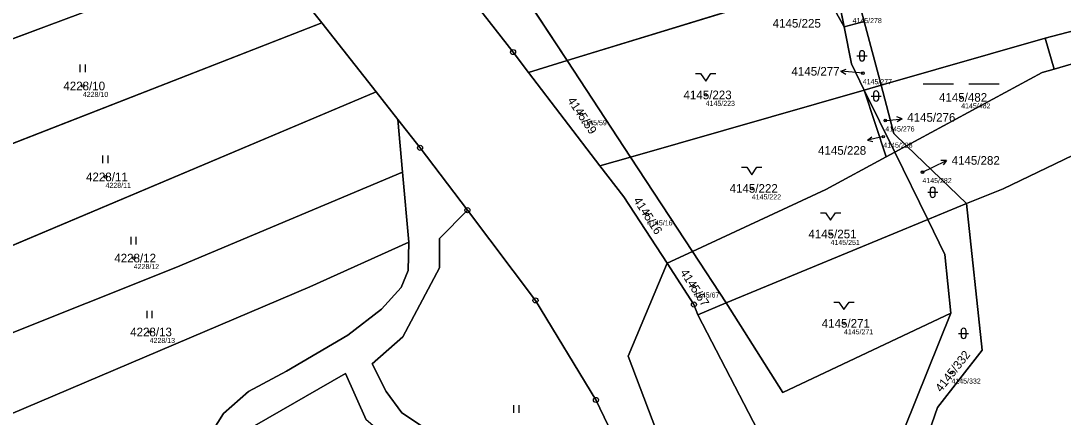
# Model space of a CAD drawing. Extents: x -739214 to -733252, y -1147612 to -1142842.
# Drawn here: x -736633.4 to -736428.1, y -1146634 to -1146556 of the extents above; entities that cross this region are included whole.
import ezdxf

# ---------------------------------------------------------------- set-up
doc = ezdxf.new("R2010")
doc.units = 0
for name, color, linetype in [('Definiční body', 7, 'Continuous'), ('Hranice parcel', 7, 'Continuous'), ('Parcelní čísla', 7, 'Continuous'), ('Polygon parcely', 7, 'Continuous'), ('Pop  PČ popisy', 7, 'Continuous'), ('Značky bodu BP', 7, 'Continuous'), ('Značky kultur', 7, 'Continuous')]:
    doc.layers.add(name, color=color, linetype=linetype)

msp = doc.modelspace()

# ---------------------------------------------------------------- linework, layer by layer
at = {"layer": 'Definiční body'}
for centre in [(-736467.6, -1146566.26), (-736621.18, -1146568.77), (-736498.53, -1146570.53), (-736448.22, -1146571.02), (-736523, -1146574.35), (-736463.16, -1146575.57), (-736463.56, -1146578.75), (-736455.85, -1146585.73), (-736616.71, -1146586.67), (-736489.45, -1146588.94), (-736510.05, -1146594.06), (-736473.94, -1146597.91), (-736611.15, -1146602.65), (-736500.83, -1146608.26), (-736608.02, -1146617.2), (-736471.31, -1146615.5), (-736450.13, -1146625.2)]:
    msp.add_circle(centre, 0.25, dxfattribs=at)
at = {"layer": 'Hranice parcel'}
for p, q in [((-736525.83, -1146563.74), (-736542.94, -1146537.7)), ((-736658.72, -1146568.3), (-736585.12, -1146540.83)), ((-736467.33, -1146556.06), (-736469.8, -1146546.72)), ((-736476.06, -1146548.51), (-736525.83, -1146563.74)), ((-736471.29, -1146557.11), (-736476.06, -1146548.51)), ((-736471.29, -1146557.11), (-736473.17, -1146547.68)), ((-736574.11, -1146556.35), (-736578.57, -1146550.68)), ((-736658.16, -1146589.11), (-736574.11, -1146556.35)), ((-736563.42, -1146569.94), (-736574.11, -1146556.35)), ((-736467.33, -1146556.06), (-736471.29, -1146557.11)), ((-736464, -1146568.64), (-736467.33, -1146556.06)), ((-736431.69, -1146559.38), (-736464, -1146568.64)), ((-736431.69, -1146559.38), (-736429.94, -1146565.44)), ((-736525.83, -1146563.74), (-736533.42, -1146566.09)), ((-736513.33, -1146582.77), (-736525.83, -1146563.74)), ((-736533.42, -1146566.09), (-736519.36, -1146584.5)), ((-736467.3, -1146569.58), (-736513.33, -1146582.77)), ((-736464, -1146568.64), (-736467.3, -1146569.58)), ((-736463, -1146582.72), (-736467.3, -1146569.58)), ((-736461.31, -1146581.81), (-736467.3, -1146569.58)), ((-736659.28, -1146610.36), (-736563.42, -1146569.94)), ((-736559.13, -1146575.4), (-736563.42, -1146569.94)), ((-736554.77, -1146580.95), (-736559.13, -1146575.4)), ((-736558.25, -1146585.73), (-736559.13, -1146575.4)), ((-736545.45, -1146593.22), (-736554.77, -1146580.95)), ((-736463, -1146582.72), (-736461.31, -1146581.81)), ((-736461.31, -1146581.81), (-736458.98, -1146580.55)), ((-736454.82, -1146595.05), (-736461.31, -1146581.81)), ((-736447.19, -1146591.89), (-736458.98, -1146580.55)), ((-736513.33, -1146582.77), (-736519.36, -1146584.5)), ((-736501.13, -1146601.35), (-736513.33, -1146582.77)), ((-736557.02, -1146599.49), (-736558.25, -1146585.73)), ((-736454.82, -1146595.05), (-736447.19, -1146591.89)), ((-736494.48, -1146611.47), (-736454.82, -1146595.05)), ((-736451.43, -1146601.95), (-736454.82, -1146595.05)), ((-736506.14, -1146603.68), (-736501.13, -1146601.35)), ((-736494.48, -1146611.47), (-736501.13, -1146601.35)), ((-736450.23, -1146613.49), (-736451.43, -1146601.95)), ((-736494.48, -1146611.47), (-736500.11, -1146613.8)), ((-736500.11, -1146613.8), (-736488.24, -1146636.62))]:
    msp.add_line(p, q, dxfattribs=at)
for points in [[(-736429.94, -1146565.44), (-736339.52, -1146538.9), (-736337.25, -1146534.6), (-736431.69, -1146559.38)], [(-736447.19, -1146591.89), (-736439.96, -1146588.99), (-736395.44, -1146567.64), (-736364.43, -1146560.32), (-736344.54, -1146555.23), (-736308.59, -1146573.63), (-736302.45, -1146556.76), (-736312.57, -1146537.18)], [(-736553, -1146540.95), (-736536.46, -1146562.1), (-736533.42, -1146566.09)], [(-736467.3, -1146569.58), (-736469.84, -1146564.41), (-736471.29, -1146557.11)], [(-736458.98, -1146580.55), (-736432.29, -1146566.13), (-736429.94, -1146565.44)], [(-736458.98, -1146580.55), (-736461.49, -1146578.14), (-736464, -1146568.64)], [(-736501.13, -1146601.35), (-736474.85, -1146589.12), (-736463, -1146582.72)], [(-736656.03, -1146625.69), (-736602.87, -1146604.51), (-736558.25, -1146585.73)], [(-736519.36, -1146584.5), (-736514.68, -1146590.62), (-736506.14, -1146603.68)], [(-736446.12, -1146664.77), (-736455.11, -1146638.49), (-736452.89, -1146632.08), (-736444.11, -1146620.77), (-736447.19, -1146591.89)], [(-736545.45, -1146593.22), (-736550.98, -1146598.79), (-736550.98, -1146604.55), (-736558.14, -1146618.12), (-736564.23, -1146623.46), (-736561.45, -1146628.91), (-736558.35, -1146633.08), (-736546.18, -1146641.2), (-736541.16, -1146645.36), (-736539.55, -1146648.78), (-736538.61, -1146656.96)], [(-736509.65, -1146652.42), (-736520.15, -1146630.58), (-736532.04, -1146610.98), (-736545.45, -1146593.22)], [(-736650.47, -1146639.75), (-736576.48, -1146608.33), (-736557.02, -1146599.49)], [(-736615.59, -1146662.7), (-736613.37, -1146659.3), (-736608.45, -1146653.82), (-736602.19, -1146647.11), (-736593.46, -1146633.23), (-736588.56, -1146628.91), (-736581.07, -1146624.89), (-736568.99, -1146617.84), (-736562.39, -1146612.69), (-736558.47, -1146608.44), (-736557.13, -1146605.08), (-736557.02, -1146599.49)], [(-736473.74, -1146679.1), (-736501.96, -1146653.1), (-736513.77, -1146621.93), (-736506.14, -1146603.68)], [(-736506.14, -1146603.68), (-736500.84, -1146611.78), (-736500.11, -1146613.8)], [(-736450.23, -1146613.49), (-736483.35, -1146629.09), (-736494.48, -1146611.47)], [(-736449.18, -1146674.88), (-736461.75, -1146642.02), (-736450.23, -1146613.49)], [(-736562.32, -1146637.09), (-736565.4, -1146634.47), (-736569.46, -1146625.39), (-736587.4, -1146635.64), (-736590.61, -1146638.74), (-736596.04, -1146648.74), (-736606.3, -1146660.49), (-736609.82, -1146666.47), (-736610.25, -1146670.85), (-736609.18, -1146673.63), (-736604.38, -1146677.69), (-736598.61, -1146681.53), (-736591.56, -1146688.26), (-736588.67, -1146694.43), (-736582.05, -1146714.94), (-736578.89, -1146719.08)]]:
    msp.add_lwpolyline(points, dxfattribs=at)
at = {"layer": 'Polygon parcely'}
for points in [[(-736476.06, -1146548.51), (-736480.2, -1146538.83), (-736489.9, -1146520.56), (-736542.94, -1146537.7), (-736525.83, -1146563.74)], [(-736593.58, -1146525.58), (-736661.58, -1146551.89), (-736661.29, -1146553.19), (-736658.72, -1146568.3), (-736585.12, -1146540.83)], [(-736431.69, -1146559.38), (-736429.94, -1146565.44), (-736339.52, -1146538.9), (-736337.25, -1146534.6)], [(-736536.46, -1146562.1), (-736533.42, -1146566.09), (-736525.83, -1146563.74), (-736542.94, -1146537.7), (-736553, -1146540.95)], [(-736585.12, -1146540.83), (-736658.72, -1146568.3), (-736657.71, -1146577.58), (-736658.16, -1146589.11), (-736574.11, -1146556.35), (-736578.57, -1146550.68), (-736583.5, -1146553.48), (-736588.45, -1146544.55), (-736584.27, -1146542.36)], [(-736467.33, -1146556.06), (-736469.8, -1146546.72), (-736473.17, -1146547.68), (-736471.29, -1146557.11)], [(-736467.3, -1146569.58), (-736469.84, -1146564.41), (-736471.29, -1146557.11), (-736476.06, -1146548.51), (-736525.83, -1146563.74), (-736513.33, -1146582.77)], [(-736471.29, -1146557.11), (-736473.17, -1146547.68), (-736476.06, -1146548.51)], [(-736659.28, -1146610.36), (-736563.42, -1146569.94), (-736574.11, -1146556.35), (-736658.16, -1146589.11)], [(-736464, -1146568.64), (-736467.33, -1146556.06), (-736471.29, -1146557.11), (-736469.84, -1146564.41), (-736467.3, -1146569.58)], [(-736458.98, -1146580.55), (-736432.29, -1146566.13), (-736429.94, -1146565.44), (-736431.69, -1146559.38), (-736464, -1146568.64), (-736461.49, -1146578.14)], [(-736525.83, -1146563.74), (-736533.42, -1146566.09), (-736519.36, -1146584.5), (-736513.33, -1146582.77)], [(-736501.13, -1146601.35), (-736474.85, -1146589.12), (-736463, -1146582.72), (-736467.3, -1146569.58), (-736513.33, -1146582.77)], [(-736467.3, -1146569.58), (-736461.31, -1146581.81), (-736458.98, -1146580.55), (-736461.49, -1146578.14), (-736464, -1146568.64)], [(-736463, -1146582.72), (-736461.31, -1146581.81), (-736467.3, -1146569.58)], [(-736656.03, -1146625.69), (-736602.87, -1146604.51), (-736558.25, -1146585.73), (-736559.13, -1146575.4), (-736563.42, -1146569.94), (-736659.28, -1146610.36), (-736659.39, -1146612.71)], [(-736494.48, -1146611.47), (-736454.82, -1146595.05), (-736461.31, -1146581.81), (-736463, -1146582.72), (-736474.85, -1146589.12), (-736501.13, -1146601.35)], [(-736454.82, -1146595.05), (-736447.19, -1146591.89), (-736458.98, -1146580.55), (-736461.31, -1146581.81)], [(-736506.14, -1146603.68), (-736501.13, -1146601.35), (-736513.33, -1146582.77), (-736519.36, -1146584.5), (-736514.68, -1146590.62)], [(-736650.47, -1146639.75), (-736576.48, -1146608.33), (-736557.02, -1146599.49), (-736558.25, -1146585.73), (-736602.87, -1146604.51), (-736656.03, -1146625.69)], [(-736446.12, -1146664.77), (-736455.11, -1146638.49), (-736452.89, -1146632.08), (-736444.11, -1146620.77), (-736447.19, -1146591.89), (-736454.82, -1146595.05), (-736451.43, -1146601.95), (-736450.23, -1146613.49), (-736461.75, -1146642.02), (-736449.18, -1146674.88)], [(-736520.15, -1146630.58), (-736532.04, -1146610.98), (-736545.45, -1146593.22), (-736550.98, -1146598.79), (-736550.98, -1146604.55), (-736558.14, -1146618.12), (-736564.23, -1146623.46), (-736561.45, -1146628.91), (-736558.35, -1146633.08), (-736546.18, -1146641.2), (-736541.16, -1146645.36), (-736539.55, -1146648.78), (-736538.61, -1146656.96), (-736509.65, -1146652.42)], [(-736451.43, -1146601.95), (-736454.82, -1146595.05), (-736494.48, -1146611.47), (-736483.35, -1146629.09), (-736450.23, -1146613.49)], [(-736557.13, -1146605.08), (-736557.02, -1146599.49), (-736576.48, -1146608.33), (-736650.47, -1146639.75), (-736650, -1146641.67), (-736644, -1146658.32), (-736615.59, -1146662.7), (-736613.37, -1146659.3), (-736608.45, -1146653.82), (-736602.19, -1146647.11), (-736593.46, -1146633.23), (-736588.56, -1146628.91), (-736581.07, -1146624.89), (-736568.99, -1146617.84), (-736562.39, -1146612.69), (-736558.47, -1146608.44)], [(-736500.11, -1146613.8), (-736494.48, -1146611.47), (-736501.13, -1146601.35), (-736506.14, -1146603.68), (-736500.84, -1146611.78)], [(-736488.24, -1146636.62), (-736500.11, -1146613.8), (-736500.84, -1146611.78), (-736506.14, -1146603.68), (-736513.77, -1146621.93), (-736501.96, -1146653.1), (-736473.74, -1146679.1), (-736479.13, -1146660.55)], [(-736467.13, -1146769.67), (-736467.49, -1146772.99), (-736383.21, -1146801.37), (-736381.77, -1146800.87), (-736378.06, -1146705.71), (-736425.61, -1146677.71), (-736449.18, -1146674.88), (-736461.75, -1146642.02), (-736450.23, -1146613.49), (-736483.35, -1146629.09), (-736494.48, -1146611.47), (-736500.11, -1146613.8), (-736488.24, -1146636.62), (-736479.13, -1146660.55), (-736473.74, -1146679.1), (-736470.53, -1146684.2), (-736467.08, -1146690.31), (-736469.67, -1146697.93), (-736467.34, -1146711.33), (-736465.52, -1146735.67)], [(-736587.4, -1146635.64), (-736590.61, -1146638.74), (-736596.04, -1146648.74), (-736606.3, -1146660.49), (-736609.82, -1146666.47), (-736610.25, -1146670.85), (-736609.18, -1146673.63), (-736604.38, -1146677.69), (-736598.61, -1146681.53), (-736591.56, -1146688.26), (-736588.67, -1146694.43), (-736582.05, -1146714.94), (-736578.89, -1146719.08), (-736579.32, -1146693.66), (-736562.32, -1146637.09), (-736565.4, -1146634.47), (-736569.46, -1146625.39)]]:
    msp.add_lwpolyline(points, close=True, dxfattribs=at)
for points in [[(-736469.8, -1146546.72), (-736467.33, -1146556.06), (-736464, -1146568.64), (-736431.69, -1146559.38), (-736337.25, -1146534.6)], [(-736339.52, -1146538.9), (-736429.94, -1146565.44), (-736432.29, -1146566.13), (-736458.98, -1146580.55), (-736447.19, -1146591.89), (-736439.96, -1146588.99), (-736395.44, -1146567.64), (-736364.43, -1146560.32), (-736344.54, -1146555.23), (-736308.59, -1146573.63), (-736302.45, -1146556.76), (-736312.57, -1146537.18)], [(-736312.57, -1146537.18), (-736302.45, -1146556.76), (-736308.59, -1146573.63), (-736344.54, -1146555.23), (-736364.43, -1146560.32), (-736395.44, -1146567.64), (-736439.96, -1146588.99), (-736447.19, -1146591.89), (-736444.11, -1146620.77), (-736452.89, -1146632.08), (-736455.11, -1146638.49), (-736446.12, -1146664.77), (-736250, -1146692.16)], [(-736501.96, -1146653.1), (-736513.77, -1146621.93), (-736506.14, -1146603.68), (-736514.68, -1146590.62), (-736519.36, -1146584.5), (-736533.42, -1146566.09), (-736536.46, -1146562.1), (-736553, -1146540.95)], [(-736578.57, -1146550.68), (-736574.11, -1146556.35), (-736563.42, -1146569.94), (-736559.13, -1146575.4), (-736554.77, -1146580.95), (-736545.45, -1146593.22), (-736532.04, -1146610.98), (-736520.15, -1146630.58), (-736509.65, -1146652.42)], [(-736546.18, -1146641.2), (-736558.35, -1146633.08), (-736561.45, -1146628.91), (-736564.23, -1146623.46), (-736558.14, -1146618.12), (-736550.98, -1146604.55), (-736550.98, -1146598.79), (-736545.45, -1146593.22), (-736554.77, -1146580.95), (-736559.13, -1146575.4), (-736558.25, -1146585.73), (-736557.02, -1146599.49), (-736557.13, -1146605.08), (-736558.47, -1146608.44), (-736562.39, -1146612.69), (-736568.99, -1146617.84), (-736581.07, -1146624.89), (-736588.56, -1146628.91), (-736593.46, -1146633.23), (-736602.19, -1146647.11)], [(-736587.4, -1146635.64), (-736569.46, -1146625.39), (-736565.4, -1146634.47)]]:
    msp.add_lwpolyline(points, dxfattribs=at)
at = {"layer": 'Pop  PČ popisy'}
for p, q in [((-736471.9, -1146565.88), (-736470.86, -1146565.47)), ((-736468.91, -1146566.14), (-736471.9, -1146565.88)), ((-736471.9, -1146565.88), (-736470.95, -1146566.47)), ((-736467.6, -1146566.26), (-736468.91, -1146566.14)), ((-736463.16, -1146575.57), (-736462.84, -1146575.54)), ((-736462.84, -1146575.54), (-736459.85, -1146575.23)), ((-736459.85, -1146575.23), (-736460.9, -1146574.83)), ((-736459.85, -1146575.23), (-736460.8, -1146575.83)), ((-736466.67, -1146579.47), (-736465.81, -1146578.75)), ((-736463.75, -1146578.79), (-736466.67, -1146579.47)), ((-736466.67, -1146579.47), (-736465.59, -1146579.73)), ((-736463.56, -1146578.75), (-736463.75, -1146578.79)), ((-736453.8, -1146584.74), (-736451.1, -1146583.42)), ((-736451.1, -1146583.42), (-736452.22, -1146583.41)), ((-736451.1, -1146583.42), (-736451.78, -1146584.31)), ((-736455.85, -1146585.73), (-736453.8, -1146584.74))]:
    msp.add_line(p, q, dxfattribs=at)
at = {"layer": 'Značky bodu BP'}
for centre, radius in [((-736536.46, -1146562.1), 0.5), ((-736536.46, -1146562.1), 0.0303), ((-736554.77, -1146580.95), 0.5), ((-736554.77, -1146580.95), 0.0303), ((-736545.45, -1146593.22), 0.5), ((-736545.45, -1146593.22), 0.0303), ((-736532.04, -1146610.98), 0.5), ((-736532.04, -1146610.98), 0.0303), ((-736500.84, -1146611.78), 0.5), ((-736500.84, -1146611.78), 0.0303), ((-736520.15, -1146630.58), 0.5), ((-736520.15, -1146630.58), 0.0303)]:
    msp.add_circle(centre, radius, dxfattribs=at)
at = {"layer": 'Značky kultur'}
for p, q in [((-736468.74, -1146562.83), (-736466.74, -1146562.83)), ((-736468.24, -1146562.33), (-736468.24, -1146563.33)), ((-736467.24, -1146563.33), (-736467.24, -1146562.33)), ((-736621.69, -1146566.07), (-736621.69, -1146564.57)), ((-736620.69, -1146566.07), (-736620.69, -1146564.57)), ((-736500.53, -1146566.33), (-736499.53, -1146566.33)), ((-736499.53, -1146566.33), (-736498.53, -1146567.83)), ((-736498.53, -1146567.83), (-736497.53, -1146566.33)), ((-736497.53, -1146566.33), (-736496.53, -1146566.33)), ((-736455.71, -1146568.32), (-736449.71, -1146568.32)), ((-736446.71, -1146568.32), (-736440.71, -1146568.32)), ((-736465.97, -1146570.75), (-736463.97, -1146570.75)), ((-736465.47, -1146570.25), (-736465.47, -1146571.25)), ((-736464.47, -1146571.25), (-736464.47, -1146570.25)), ((-736617.22, -1146583.97), (-736617.22, -1146582.47)), ((-736616.22, -1146583.97), (-736616.22, -1146582.47)), ((-736491.45, -1146584.74), (-736490.45, -1146584.74)), ((-736490.45, -1146584.74), (-736489.45, -1146586.24)), ((-736489.45, -1146586.24), (-736488.45, -1146584.74)), ((-736488.45, -1146584.74), (-736487.45, -1146584.74)), ((-736454.82, -1146589.7), (-736452.82, -1146589.7)), ((-736454.32, -1146589.2), (-736454.32, -1146590.2)), ((-736453.32, -1146590.2), (-736453.32, -1146589.2)), ((-736475.94, -1146593.71), (-736474.94, -1146593.71)), ((-736474.94, -1146593.71), (-736473.94, -1146595.21)), ((-736473.94, -1146595.21), (-736472.94, -1146593.71)), ((-736472.94, -1146593.71), (-736471.94, -1146593.71)), ((-736611.66, -1146599.95), (-736611.66, -1146598.45)), ((-736610.66, -1146599.95), (-736610.66, -1146598.45)), ((-736608.53, -1146614.5), (-736608.53, -1146613)), ((-736607.53, -1146614.5), (-736607.53, -1146613)), ((-736473.31, -1146611.3), (-736472.31, -1146611.3)), ((-736472.31, -1146611.3), (-736471.31, -1146612.8)), ((-736471.31, -1146612.8), (-736470.31, -1146611.3)), ((-736470.31, -1146611.3), (-736469.31, -1146611.3)), ((-736448.25, -1146616.97), (-736448.25, -1146617.97)), ((-736447.25, -1146617.97), (-736447.25, -1146616.97)), ((-736448.75, -1146617.47), (-736446.75, -1146617.47)), ((-736536.28, -1146633.08), (-736536.28, -1146631.58)), ((-736535.28, -1146633.08), (-736535.28, -1146631.58))]:
    msp.add_line(p, q, dxfattribs=at)
for centre, start, end in [((-736467.74, -1146562.33), 0, 180), ((-736467.74, -1146563.33), 180, 359.9879), ((-736464.97, -1146570.25), 0, 180), ((-736464.97, -1146571.25), 180, 359.9879), ((-736453.82, -1146589.2), 0, 180), ((-736453.82, -1146590.2), 180, 359.9879), ((-736447.75, -1146616.97), 0, 180), ((-736447.75, -1146617.97), 180, 359.9879)]:
    msp.add_arc(centre, 0.5, start, end, dxfattribs=at)

# ---------------------------------------------------------------- texts
at = {"layer": 'Definiční body'}
for s, p in [('4145/278', (-736469.61, -1146556.4)), ('4145/277', (-736467.6, -1146568.42)), ('4228/10', (-736621.18, -1146570.93)), ('4145/223', (-736498.53, -1146572.69)), ('4145/482', (-736448.22, -1146573.18)), ('4145/59', (-736523, -1146576.51)), ('4145/276', (-736463.16, -1146577.73)), ('4145/228', (-736463.56, -1146580.91)), ('4228/11', (-736616.71, -1146588.83)), ('4145/282', (-736455.85, -1146587.89)), ('4145/222', (-736489.45, -1146591.1)), ('4145/16', (-736510.05, -1146596.22)), ('4145/251', (-736473.94, -1146600.07)), ('4228/12', (-736611.15, -1146604.81)), ('4145/67', (-736500.83, -1146610.42)), ('4145/271', (-736471.31, -1146617.66)), ('4228/13', (-736608.02, -1146619.36)), ('4145/332', (-736450.13, -1146627.36))]:
    msp.add_text(s, height=1, dxfattribs=at).set_placement(p)
at = {"layer": 'Parcelní čísla'}
for s, p in [('4145/225', (-736485.34, -1146557.28)), ('4145/277', (-736481.64, -1146566.73)), ('4228/10', (-736625.02, -1146569.62)), ('4145/223', (-736502.9, -1146571.38)), ('4145/482', (-736452.59, -1146571.87)), ('4145/276', (-736458.85, -1146575.81)), ('4145/228', (-736476.41, -1146582.31)), ('4145/282', (-736450.1, -1146584.28)), ('4228/11', (-736620.55, -1146587.52)), ('4145/222', (-736493.82, -1146589.79)), ('4145/251', (-736478.31, -1146598.76)), ('4228/12', (-736614.99, -1146603.5)), ('4145/271', (-736475.68, -1146616.35)), ('4228/13', (-736611.86, -1146618.05))]:
    msp.add_text(s, height=1.7, dxfattribs=at).set_placement(p)
for s, rotation, p in [('4145/59', 304, (-736525.85, -1146571.64)), ('4145/16', 303, (-736512.85, -1146591.3)), ('4145/67', 303, (-736503.63, -1146605.5)), ('4145/332', 52, (-736452.15, -1146629.17))]:
    msp.add_text(s, height=1.7, rotation=rotation, dxfattribs=at).set_placement(p)

doc.saveas('drawing.dxf')
